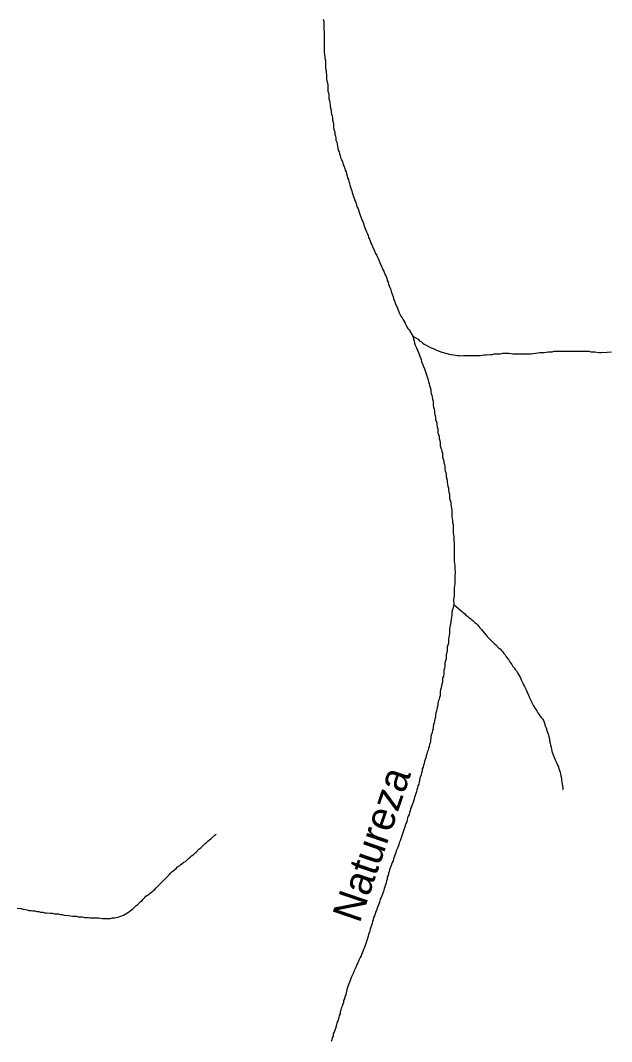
# Model space of a CAD drawing. Extents: x 652.3 to 678, y 7316.9 to 7344.9.
# Drawn here: x 664.81 to 666.424, y 7325.269 to 7328.056 of the extents above; entities that cross this region are included whole.
import ezdxf
from ezdxf.enums import TextEntityAlignment as Align

# ---------------------------------------------------------------- set-up
doc = ezdxf.new("R2010")
doc.units = 0
doc.header["$LTSCALE"] = 0.032
doc.layers.add('61', color=7, linetype='Continuous')
doc.layers.add('7', color=7, linetype='Continuous', lineweight=25)

msp = doc.modelspace()

# ---------------------------------------------------------------- linework, layer by layer
at = {"layer": '7'}
for points in [[(665.6366, 7328.0598), (665.6382, 7328.0535), (665.6382, 7328.036), (665.639, 7328.0304), (665.6398, 7328.0248), (665.6398, 7327.9691), (665.6406, 7327.9635), (665.6414, 7327.958), (665.6414, 7327.9524), (665.643, 7327.9476), (665.643, 7327.9246), (665.6446, 7327.9198), (665.6454, 7327.9134), (665.6462, 7327.9078), (665.6462, 7327.8967), (665.647, 7327.8911), (665.6486, 7327.8856), (665.6494, 7327.88), (665.6494, 7327.8633), (665.651, 7327.8585), (665.6526, 7327.8537), (665.6526, 7327.8426), (665.6541, 7327.8378), (665.6549, 7327.8323), (665.6557, 7327.8267), (665.6557, 7327.8211), (665.6589, 7327.8116), (665.6589, 7327.806), (665.6597, 7327.8004), (665.6613, 7327.7957), (665.6621, 7327.7901), (665.6621, 7327.7845), (665.6637, 7327.7789), (665.6653, 7327.7742), (665.6653, 7327.763), (665.6669, 7327.7567)], [(665.6669, 7327.7567), (665.6685, 7327.7511), (665.6685, 7327.7455), (665.6701, 7327.7407), (665.6717, 7327.7352), (665.6717, 7327.7296), (665.674, 7327.724), (665.6748, 7327.7185), (665.6756, 7327.7129), (665.6772, 7327.7081), (665.678, 7327.7026), (665.6804, 7327.6978), (665.6812, 7327.6922), (665.6836, 7327.6874), (665.6844, 7327.6819), (665.6868, 7327.6771), (665.6884, 7327.6723), (665.6907, 7327.6675), (665.6915, 7327.662), (665.6939, 7327.6572), (665.6955, 7327.6524), (665.6971, 7327.6477), (665.6995, 7327.6429), (665.7003, 7327.6373), (665.7027, 7327.6325), (665.7035, 7327.627), (665.7059, 7327.6222), (665.7067, 7327.6166), (665.709, 7327.6118), (665.7098, 7327.6063), (665.7114, 7327.6015), (665.713, 7327.5959), (665.7146, 7327.5912), (665.7162, 7327.5864), (665.7178, 7327.5816), (665.7194, 7327.576), (665.721, 7327.5713), (665.7226, 7327.5665), (665.725, 7327.5617), (665.7266, 7327.5569), (665.7281, 7327.5522), (665.7297, 7327.5466), (665.7321, 7327.5418), (665.7369, 7327.5275), (665.7385, 7327.5219), (665.7409, 7327.5172), (665.7425, 7327.5124), (665.7449, 7327.5076), (665.7496, 7327.4933), (665.7512, 7327.4885), (665.7536, 7327.4837), (665.7552, 7327.479), (665.7576, 7327.4742), (665.76, 7327.4694), (665.7608, 7327.4639), (665.7632, 7327.4591), (665.7655, 7327.4543), (665.7671, 7327.4487), (665.7695, 7327.444), (665.7711, 7327.4392), (665.7759, 7327.4296), (665.7775, 7327.4249), (665.7799, 7327.4201), (665.783, 7327.4145), (665.7854, 7327.4097), (665.7878, 7327.405), (665.7894, 7327.4002), (665.7918, 7327.3954), (665.7934, 7327.3906), (665.7982, 7327.3811), (665.7998, 7327.3763), (665.8021, 7327.3716), (665.8045, 7327.3668), (665.8061, 7327.362), (665.8085, 7327.3572), (665.8101, 7327.3525), (665.8117, 7327.3469), (665.8141, 7327.3421), (665.8149, 7327.3365), (665.8173, 7327.3318), (665.8189, 7327.327), (665.8212, 7327.3222), (665.8228, 7327.3166), (665.8276, 7327.3023), (665.8292, 7327.2976), (665.8324, 7327.288), (665.834, 7327.2824), (665.8387, 7327.2729), (665.8403, 7327.2681), (665.8427, 7327.2633), (665.8443, 7327.2586), (665.8491, 7327.249), (665.8523, 7327.2442), (665.8547, 7327.2395), (665.8578, 7327.2347), (665.8602, 7327.2299), (665.8626, 7327.2251), (665.865, 7327.2204), (665.8682, 7327.2156), (665.8714, 7327.2116), (665.8817, 7327.1941)], [(665.8817, 7327.1941), (665.896, 7327.1862), (665.9, 7327.1822), (665.9048, 7327.179), (665.9088, 7327.1758), (665.9127, 7327.1726), (665.9175, 7327.1702), (665.9247, 7327.1663), (665.9318, 7327.1623), (665.9366, 7327.1607), (665.9462, 7327.1559), (665.9605, 7327.1511), (665.9653, 7327.1496), (665.97, 7327.148), (665.9756, 7327.1472), (665.9804, 7327.1456), (665.9859, 7327.1448), (665.9923, 7327.1432), (665.9979, 7327.1424), (666.0035, 7327.1416), (666.009, 7327.1416), (666.0146, 7327.1408), (666.0202, 7327.1416), (666.0655, 7327.1416), (666.0711, 7327.1424), (666.0767, 7327.1432), (666.0822, 7327.1432), (666.0934, 7327.1448), (666.0989, 7327.1448), (666.1037, 7327.1464), (666.1204, 7327.1464), (666.1268, 7327.148), (666.1435, 7327.148), (666.1491, 7327.1472), (666.1546, 7327.1464), (666.2048, 7327.1464), (666.2103, 7327.1472), (666.2159, 7327.148), (666.2223, 7327.1488), (666.2278, 7327.1496), (666.2342, 7327.1503), (666.2398, 7327.1503), (666.2453, 7327.1511), (666.2509, 7327.1519), (666.2621, 7327.1519), (666.2676, 7327.1535), (666.3623, 7327.1535), (666.3671, 7327.1519), (666.3782, 7327.1519), (666.3838, 7327.1511), (666.3902, 7327.1503), (666.3957, 7327.1503), (666.4124, 7327.1511), (666.4236, 7327.1517), (666.424, 7327.1517)], [(665.8817, 7327.1941), (665.8849, 7327.1806), (665.8865, 7327.1758)], [(665.8865, 7327.1758), (665.8881, 7327.1702), (665.8913, 7327.1623), (665.8968, 7327.1503), (665.8984, 7327.1448), (665.9008, 7327.14), (665.904, 7327.1305), (665.9056, 7327.1257), (665.9104, 7327.1114), (665.9135, 7327.1058), (665.9151, 7327.1002), (665.9199, 7327.0859), (665.9215, 7327.0811), (665.9231, 7327.0756), (665.9247, 7327.07), (665.9263, 7327.0652), (665.9271, 7327.0596), (665.9287, 7327.0541), (665.9303, 7327.0493), (665.931, 7327.0437), (665.9318, 7327.0382), (665.9334, 7327.0334), (665.9342, 7327.0278), (665.935, 7327.0222), (665.9366, 7327.0175), (665.9374, 7327.0119), (665.9374, 7327.0063), (665.9382, 7327.0008), (665.9398, 7326.9952), (665.9406, 7326.9896), (665.9406, 7326.9841), (665.9438, 7326.9729), (665.9438, 7326.9673), (665.9454, 7326.9626), (665.947, 7326.9578), (665.947, 7326.9522), (665.9478, 7326.9467), (665.9493, 7326.9419), (665.9501, 7326.9363), (665.9501, 7326.9307), (665.9517, 7326.926), (665.9533, 7326.9212), (665.9533, 7326.9156), (665.9565, 7326.9061), (665.9565, 7326.8949), (665.9581, 7326.8902), (665.9597, 7326.8854), (665.9605, 7326.8798), (665.9621, 7326.875), (665.9629, 7326.8695), (665.9629, 7326.8639), (665.9661, 7326.8544), (665.9661, 7326.8488), (665.9676, 7326.844), (665.9692, 7326.8384), (665.9692, 7326.8329), (665.97, 7326.8273), (665.9716, 7326.8225), (665.9724, 7326.817), (665.9724, 7326.8114), (665.9756, 7326.8018), (665.9756, 7326.7963), (665.9764, 7326.7907), (665.9772, 7326.7851), (665.9788, 7326.7796), (665.9788, 7326.774), (665.9796, 7326.7684), (665.9812, 7326.7636), (665.982, 7326.7581), (665.982, 7326.7525), (665.9836, 7326.7461), (665.9852, 7326.7414), (665.9852, 7326.735), (665.9859, 7326.7294), (665.9875, 7326.7247), (665.9883, 7326.7191), (665.9883, 7326.7024), (665.9891, 7326.6968), (665.9899, 7326.6912), (665.9899, 7326.6857), (665.9915, 7326.6809), (665.9915, 7326.6578), (665.9923, 7326.6522), (665.9931, 7326.6467), (665.9931, 7326.6355), (665.9939, 7326.63), (665.9947, 7326.6244), (665.9947, 7326.5798), (665.9955, 7326.5743), (665.9963, 7326.5687), (665.9963, 7326.5576), (665.9971, 7326.552), (665.9971, 7326.5464), (665.9963, 7326.5409), (665.9963, 7326.5186), (665.9955, 7326.513), (665.9947, 7326.5074), (665.9947, 7326.4852), (665.9931, 7326.4804), (665.9923, 7326.4748), (665.9931, 7326.4621)], [(665.9931, 7326.4621), (665.9907, 7326.4501), (665.9891, 7326.4454), (665.9883, 7326.4398), (665.9883, 7326.4342), (665.9867, 7326.4263), (665.9852, 7326.4175), (665.9852, 7326.412), (665.9836, 7326.4056), (665.9828, 7326.4), (665.982, 7326.3944), (665.982, 7326.3833), (665.9804, 7326.3785), (665.9796, 7326.373), (665.9788, 7326.3674), (665.9788, 7326.3563), (665.9772, 7326.3515), (665.9756, 7326.3467), (665.9756, 7326.3356), (665.974, 7326.3308), (665.9724, 7326.3252), (665.9724, 7326.3141), (665.9708, 7326.3085), (665.9692, 7326.3037), (665.9692, 7326.2926), (665.9676, 7326.2878), (665.9661, 7326.283), (665.9661, 7326.2719), (665.9653, 7326.2663), (665.9629, 7326.2616), (665.9629, 7326.2504), (665.9597, 7326.2409), (665.9589, 7326.2345), (665.9573, 7326.2297), (665.9565, 7326.2242), (665.9565, 7326.2186), (665.9557, 7326.213), (665.9541, 7326.2083), (665.9533, 7326.2027), (665.9509, 7326.1979), (665.9501, 7326.1923), (665.9493, 7326.1868), (665.9478, 7326.182), (665.947, 7326.1764), (665.9462, 7326.1709), (665.9446, 7326.1661), (665.9438, 7326.1605), (665.9438, 7326.1549), (665.9414, 7326.1502), (665.9406, 7326.1446), (665.9398, 7326.139), (665.9382, 7326.1343), (665.9374, 7326.1287), (665.9366, 7326.1231), (665.935, 7326.1183), (665.9342, 7326.1128), (665.931, 7326.1032)], [(665.9931, 7326.4621), (666.0066, 7326.4509), (666.0138, 7326.4446), (666.0226, 7326.4374), (666.0265, 7326.4334), (666.0305, 7326.4303), (666.0345, 7326.4271), (666.0385, 7326.4239), (666.0424, 7326.4207), (666.0464, 7326.4175), (666.0504, 7326.4135), (666.0544, 7326.4104), (666.0584, 7326.4064), (666.0615, 7326.4024), (666.0647, 7326.3984), (666.0687, 7326.3944), (666.0846, 7326.3746), (666.0886, 7326.3706), (666.0926, 7326.3666), (666.0965, 7326.3634), (666.0997, 7326.3594), (666.1037, 7326.3555), (666.1077, 7326.3523), (666.1156, 7326.3443), (666.1196, 7326.3411), (666.1228, 7326.3372), (666.1268, 7326.3332), (666.13, 7326.3284), (666.1332, 7326.3244), (666.1363, 7326.3197), (666.1427, 7326.3117), (666.1451, 7326.3069), (666.1483, 7326.3029), (666.1515, 7326.2982), (666.1546, 7326.2934), (666.1578, 7326.2894), (666.161, 7326.2846), (666.1642, 7326.2807), (666.1674, 7326.2759), (666.1698, 7326.2711), (666.1729, 7326.2663), (666.1753, 7326.2616), (666.1769, 7326.2568), (666.1817, 7326.2472), (666.1833, 7326.2425), (666.1865, 7326.2385), (666.1912, 7326.2289), (666.1928, 7326.2242), (666.1952, 7326.2194), (666.1976, 7326.2146), (666.1992, 7326.2098), (666.2016, 7326.2051), (666.204, 7326.2003), (666.2111, 7326.186), (666.2135, 7326.1812), (666.2199, 7326.1717), (666.2223, 7326.1669), (666.2255, 7326.1629), (666.2286, 7326.1581), (666.2318, 7326.1541), (666.2358, 7326.1502), (666.2382, 7326.1454), (666.2398, 7326.1406), (666.243, 7326.1311), (666.2453, 7326.1255), (666.2485, 7326.116), (666.2501, 7326.1112), (666.2517, 7326.1064), (666.2525, 7326.1008), (666.2541, 7326.0953), (666.2549, 7326.0897), (666.2565, 7326.0841), (666.2573, 7326.0786), (666.2589, 7326.073), (666.2597, 7326.0674), (666.2613, 7326.0618), (666.2644, 7326.0523), (666.266, 7326.0475), (666.2684, 7326.0428), (666.27, 7326.038), (666.2724, 7326.0332), (666.2748, 7326.0284), (666.2764, 7326.0237), (666.2788, 7326.0189), (666.2804, 7326.0141), (666.2819, 7326.0093), (666.2835, 7326.0046), (666.2843, 7325.999), (666.2859, 7325.9942), (666.2875, 7325.9886), (666.2875, 7325.9831), (666.2883, 7325.9775), (666.2907, 7325.9616), (666.2914, 7325.9569), (666.2915, 7325.9565)], [(665.931, 7326.1032), (665.931, 7326.0977), (665.9295, 7326.0929), (665.9295, 7326.0873), (665.9271, 7326.0801), (665.9263, 7326.0746), (665.9239, 7326.0698), (665.9231, 7326.0642), (665.9207, 7326.0595), (665.9199, 7326.0539), (665.9175, 7326.0491), (665.9167, 7326.0435), (665.9151, 7326.0388), (665.9135, 7326.034), (665.9127, 7326.0284), (665.9104, 7326.0237), (665.9096, 7326.0181), (665.9072, 7326.0133), (665.9072, 7326.0077), (665.9048, 7326.003), (665.904, 7325.9974), (665.9024, 7325.9926), (665.9008, 7325.9878), (665.9, 7325.9823), (665.8984, 7325.9775), (665.8976, 7325.9719), (665.8952, 7325.9672), (665.8944, 7325.9616), (665.8921, 7325.9568), (665.8913, 7325.9512), (665.8897, 7325.9465), (665.8881, 7325.9409), (665.8865, 7325.9361), (665.8849, 7325.9306), (665.8833, 7325.9258), (665.8817, 7325.9202), (665.8793, 7325.9154), (665.8777, 7325.9099), (665.8753, 7325.9051), (665.8746, 7325.8995), (665.8722, 7325.8948), (665.8714, 7325.8892), (665.869, 7325.8844), (665.8674, 7325.8796), (665.8658, 7325.8749), (665.865, 7325.8693), (665.8626, 7325.8645), (665.8594, 7325.855), (665.8578, 7325.8502), (665.8531, 7325.8359), (665.8515, 7325.8311), (665.8467, 7325.8168), (665.8443, 7325.812), (665.8435, 7325.8064), (665.8411, 7325.8017), (665.8395, 7325.7969), (665.8372, 7325.7921), (665.834, 7325.7826), (665.8324, 7325.7778), (665.8292, 7325.7682), (665.8276, 7325.7627), (665.8252, 7325.7579), (665.8236, 7325.7523), (665.8212, 7325.7476), (665.8181, 7325.738), (665.8165, 7325.7332), (665.8149, 7325.7285), (665.8141, 7325.7229), (665.8117, 7325.7181), (665.8117, 7325.7125), (665.8093, 7325.7078), (665.8085, 7325.7022), (665.8069, 7325.6974), (665.8053, 7325.6919), (665.8037, 7325.6871), (665.8021, 7325.6815), (665.8006, 7325.6767), (665.799, 7325.672), (665.7966, 7325.6672), (665.795, 7325.6624), (665.7926, 7325.6576), (665.7918, 7325.6521), (665.7894, 7325.6473), (665.7878, 7325.6425), (665.7862, 7325.6377), (665.7838, 7325.633), (665.7823, 7325.6274), (665.7799, 7325.6226), (665.7783, 7325.6179), (665.7767, 7325.6123), (665.7743, 7325.6075), (665.7735, 7325.6019), (665.7711, 7325.5972), (665.7703, 7325.5916), (665.7687, 7325.5868), (665.7671, 7325.5813), (665.7655, 7325.5765), (665.764, 7325.5709), (665.7624, 7325.5661), (665.7608, 7325.5614), (665.7592, 7325.5566)], [(664.8012, 7325.6338), (664.8123, 7325.6322), (664.8179, 7325.6306), (664.8234, 7325.6298), (664.829, 7325.629), (664.8338, 7325.6274), (664.8394, 7325.6274), (664.8441, 7325.6258), (664.8497, 7325.6258), (664.8553, 7325.6242), (664.8608, 7325.6242), (664.8656, 7325.6226), (664.8712, 7325.6226), (664.876, 7325.621), (664.8815, 7325.621), (664.8927, 7325.6194), (664.8982, 7325.6194), (664.903, 7325.6179), (664.9142, 7325.6179), (664.9189, 7325.6163), (664.9245, 7325.6163), (664.9301, 7325.6147), (664.9412, 7325.6131), (664.9468, 7325.6123), (664.9523, 7325.6115), (664.9635, 7325.6115), (664.9683, 7325.6099), (664.9794, 7325.6099), (664.985, 7325.6083), (664.9961, 7325.6083), (665.0009, 7325.6067), (665.0232, 7325.6067), (665.0287, 7325.6059), (665.0343, 7325.6051), (665.0566, 7325.6051), (665.0614, 7325.6067), (665.0669, 7325.6067), (665.0717, 7325.6083), (665.0773, 7325.6091), (665.082, 7325.6107), (665.0868, 7325.6123), (665.0916, 7325.6147), (665.0964, 7325.6171), (665.1011, 7325.6194), (665.1051, 7325.6226), (665.1099, 7325.6258), (665.1139, 7325.629), (665.1179, 7325.6322), (665.1218, 7325.6362), (665.1258, 7325.6401), (665.1306, 7325.6433), (665.1385, 7325.6513), (665.1425, 7325.6545), (665.1457, 7325.6584), (665.1497, 7325.6624), (665.1529, 7325.6664), (665.1576, 7325.6688), (665.1616, 7325.672), (665.1656, 7325.6751), (665.1696, 7325.6783), (665.1736, 7325.6815), (665.1775, 7325.6847), (665.1807, 7325.6887), (665.2046, 7325.7125), (665.2086, 7325.7165), (665.2165, 7325.7245), (665.2197, 7325.7285), (665.2237, 7325.7324), (665.2277, 7325.7356), (665.2316, 7325.7388), (665.2356, 7325.742), (665.2396, 7325.746), (665.2444, 7325.7491), (665.2483, 7325.7523), (665.2523, 7325.7555), (665.2563, 7325.7587), (665.2611, 7325.7611), (665.269, 7325.769), (665.2738, 7325.7722), (665.2778, 7325.7762), (665.2818, 7325.7794), (665.2857, 7325.7826), (665.2897, 7325.7865), (665.2977, 7325.7945), (665.3025, 7325.7977), (665.3064, 7325.8017), (665.3104, 7325.8056), (665.3144, 7325.8096), (665.3184, 7325.8128), (665.3223, 7325.816), (665.3263, 7325.82), (665.3303, 7325.8231), (665.3422, 7325.8335), (665.3446, 7325.8356), (665.3449, 7325.8358)], [(665.7592, 7325.5566), (665.7576, 7325.551), (665.7528, 7325.5367), (665.7512, 7325.5319), (665.748, 7325.5224), (665.7457, 7325.5176), (665.7441, 7325.5128), (665.7417, 7325.508), (665.7401, 7325.5033), (665.7377, 7325.4985), (665.7353, 7325.4937), (665.7329, 7325.489), (665.7313, 7325.4842), (665.7289, 7325.4794), (665.7266, 7325.4746), (665.725, 7325.4699), (665.7202, 7325.4603), (665.7186, 7325.4555), (665.7138, 7325.446), (665.7122, 7325.4412), (665.7106, 7325.4364), (665.709, 7325.4317), (665.7067, 7325.4269), (665.7051, 7325.4221), (665.7035, 7325.4165), (665.7011, 7325.4118), (665.6995, 7325.4022), (665.6987, 7325.3967), (665.6963, 7325.3919), (665.6947, 7325.3863), (665.6923, 7325.3815), (665.6923, 7325.376), (665.69, 7325.3712), (665.6884, 7325.3656), (665.686, 7325.3608), (665.6852, 7325.3553), (665.6836, 7325.3505), (665.6828, 7325.3449), (665.6804, 7325.3402), (665.6796, 7325.3346), (665.6764, 7325.325), (665.674, 7325.3203), (665.6732, 7325.3147), (665.6701, 7325.3051), (665.6685, 7325.3004), (665.6669, 7325.2948), (665.6645, 7325.29), (665.6637, 7325.2845), (665.6613, 7325.2797), (665.6605, 7325.2741), (665.6589, 7325.2693)]]:
    msp.add_lwpolyline(points, dxfattribs=at)

# ---------------------------------------------------------------- texts
at = {"layer": '61'}
msp.add_text('Natureza', height=0.08, rotation=71.059, dxfattribs=at).set_placement((665.8066, 7325.7952), align=Align.CENTER)

doc.saveas('drawing.dxf')
